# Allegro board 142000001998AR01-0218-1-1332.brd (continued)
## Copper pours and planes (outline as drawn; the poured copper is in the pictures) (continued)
GND on BOTTOM: 136.75,58.37 136.25,57.86 136.25,54.79 135.41,53.95 133.25,53.95 133.07,53.77 133.07,50.7 133.63,50.14 138.28,50.14 139.06,50.93 139.06,57.99 138.68,58.37
GND on BOTTOM: 71.4,25.48 71.07,25.81 71.07,27.25 71.27,27.46 83.41,27.46 83.59,27.28 83.59,25.43 82.73,24.56 73.15,24.56 72.24,25.48
GND on BOTTOM: 79.27,62.2 82.55,62.2 84.28,60.48 84.28,56.21 83.44,55.37 79.55,55.37 79.17,55.75 79.17,62.1
GND on BOTTOM: 166.12,29.34 166.12,31.5 167.08,32.46 167.08,34.29 167.59,34.8 170.66,34.8 170.94,34.52 170.94,31.85 171.65,31.14 172.36,31.14 173.05,30.45 173.05,29.69 172.29,28.93 166.52,28.93
GND on BOTTOM: 72.77,22.4 66.47,22.4 65.86,21.79 64.57,21.79 64.41,21.64 64.41,20.88 64.52,20.78 72.8,20.78 72.9,20.88 72.9,22.28
GND on BOTTOM: 26.04,25.02 30.61,25.02 31.5,24.13 31.5,23.37 30.99,22.86 29.46,22.86 29.08,22.48 29.08,21.84 28.7,21.46 25.78,21.46 25.4,21.84 25.4,24.38
GND on BOTTOM: 1.68,16.66 7.39,16.66 7.92,16.13 7.92,11.28 7.34,10.69 2.36,10.69 1.47,11.58 1.47,16.46
GND on BOTTOM: 175.03,83.19 175.03,82.37 174.9,82.25 174.19,82.25 173.74,82.7 172.82,82.7 172.72,82.8 172.72,86.51 173,86.79 175.06,86.79 175.29,86.56 175.29,85.85 174.96,85.52 174.19,85.52 173.96,85.29 173.96,83.44 174.17,83.24 174.98,83.24
GND on BOTTOM: 164.77,35.81 164.77,42.82 165.28,43.33 165.28,45.69 165.48,45.9 166.29,45.9 166.47,46.08 166.47,48.59 165.71,49.35 165.71,50.6 165.99,50.88 168.73,50.88 170.51,49.1 170.51,44.3 168.61,42.39 166.62,42.39 166.27,42.04 166.27,35.97 165.89,35.59 165,35.59
GND on BOTTOM: 44.88,27.53 55.78,27.53 56.79,28.55 56.79,33.45 57.18,33.83 57.18,36.04 57.19,36.06 57.19,37.4 57.4,37.62 58.55,37.62 58.83,37.34 58.83,23.9 56.52,21.59 55.65,21.59 55.52,21.72 55.52,24.21 56.36,25.04 56.36,25.45 56.03,25.78 55.58,25.78 54.58,24.79 53.85,24.79 52.68,23.62 48.74,23.62 48.26,23.14 48.26,22.15 47.73,21.62 44.63,21.62 43.97,22.28 43.97,25.58 44.36,25.97 44.36,27.01
GND on BOTTOM: 111.56,71.68 110.92,71.68 110.87,71.73 110.87,74.02 111.05,74.19 113.49,74.19 113.77,74.47 113.77,77.17 113.06,77.88 113.06,79.38 112.8,79.63 110.67,79.63 110.54,79.76 110.54,80.06 110.69,80.21 116.03,80.21 116.54,79.71 116.54,73.08 120.32,69.29 120.32,68.43 119.46,67.56 115.32,67.56 114.76,68.12 114.76,72.11 114.02,72.85 112.73,72.85
GND on BOTTOM: 96.39,51.99 97.59,51.99 97.92,51.66 97.92,50.34 97.56,49.99 96.6,49.99 96.29,50.29 96.29,51.89
GND on BOTTOM: 41.5,14.96 47.4,14.96 47.98,14.38 47.98,12.65 46.84,11.51 42.16,11.51 41.1,12.57 41.1,14.55
GND on BOTTOM: 90.47,52.63 91.82,52.63 92.15,52.3 92.15,48.9 92.02,48.77 91.39,48.77 90.83,49.33 89.66,49.33 89.08,48.74 89.08,46.91 88.62,46.46 88.06,46.46 87.68,46.84 87.68,49.83
GND on BOTTOM: 162.69,10.19 167.34,10.19 167.49,10.03 167.49,8.81 167.06,8.38 167.06,5.13 166.7,4.78 163.32,4.78 162.41,5.69 162.41,9.91
GND on BOTTOM: 77.83,44.25 78.05,44.02 78.05,42.65 84.1,36.6 84.1,35.79 84.02,35.71 73.2,35.71 72.95,35.46 72.95,34.8 72.85,34.7 69.01,34.7 68.3,33.99 65.94,33.99 65.79,34.14 65.79,35.62 69.29,39.13 69.29,43.74 69.8,44.25
GND on BOTTOM: 187.74,116.66 189.69,116.66 190.01,116.34 190.01,112.81 189.76,112.56 187.12,112.56 186.84,112.84 186.84,115.76
GND on BOTTOM: 7.03,91.27 7.03,95.54 8.34,96.86 14.9,96.86 15.72,96.03 15.72,91.08 13.54,88.9 9.41,88.9
GND on G2: 0.26,0.26 0.26,123.24 209.7,123.24 209.73,123.22 209.73,0.3 209.68,0.26
GND on G4, G9: 0.26,0.26 0.26,123.24 209.7,123.24 209.73,123.22 209.73,0.3 209.68,0.26
GND on S5: 101.28,75.76 101.28,74.65 101,74.37 97.69,74.37 97.13,73.81 97.13,72.19 97.51,71.81 101.96,71.81 102.11,71.65 102.11,71.4 101.57,70.87 101.57,69.47 101.32,69.22 100.71,69.22 99.95,68.45 99.95,64.47 99.62,64.13 96.52,64.13 96.47,64.14 86.49,64.14 84.71,62.36 84.71,58.55 83.95,57.78 80.14,57.78 79.38,58.55 79.38,77.22 80.52,78.36 85.47,78.36 86.11,78.99 86.11,82.68 86.23,82.8 93.22,82.8 93.47,82.55 93.47,80.9 94.49,79.88 99.82,79.88 100.33,79.38 100.33,76.71
GND on V6: 55.65,37.19 54.05,37.19 53.3,37.93 38.76,37.93 38.08,38.61 32.59,38.61 30.84,40.36 30.84,52.45 30.2,53.09 2.06,53.09 0.69,51.71 0.38,51.71 0.3,51.79 0.3,86.44 2.79,83.95 27,83.95 28.91,85.85 28.91,107.85 32.08,111.02 55.85,111.02 61.09,105.79 65.66,105.79 68.71,102.74 68.71,100.84 70.87,98.68 93.73,98.68 95.15,97.26 95.15,93.7 96.27,92.58 96.27,88.27 93.85,85.85 93.85,85.8 93.22,85.17 93.22,73.28 92.84,72.9 88.9,72.9 88.39,72.39 88.39,71.45 88.9,70.94 88.9,70.79 88.39,70.28 88.39,68.28 88.9,67.77 88.9,67.41 88.39,66.9 88.39,66.42 90.55,64.26 92.28,64.26 92.89,63.65 92.89,63.02 92.71,62.84 92.71,62.28 92.89,62.1 92.89,61.62 92.69,61.43 92.69,60.33 93.14,59.88 93.14,51.1 77.09,35.05 57.78,35.05
GND on V6: 0.33,0.28 0.29,0.29 0.28,0.33 0.28,123.17 0.29,123.21 0.33,123.22 141.94,123.22 141.94,122.59 0.91,122.59 0.91,0.91 126.16,0.91 126.59,0.48 127.23,0.48 127.66,0.91 160.05,0.91 160.48,0.48 161.14,0.48 161.57,0.91 185.09,0.91 207.85,0.91 208.33,1.4 208.33,122.02 207.77,122.59 151.51,122.59 151.51,123.22 209.67,123.22 209.73,123.16 209.73,0.33 209.68,0.28
GND on V6, V7: 141.17,122.59 142.39,122.59 143.46,121.51 151.58,121.51 152.65,122.59 152.78,122.59 152.78,123.22 141.17,123.22
GND on V7: 6.35,122.43 6.86,121.92 6.86,109.6 11.94,104.52 12.45,104.52 12.57,104.65 51.56,104.65 51.82,104.9 56.39,104.9 59.44,107.95 60.07,107.95 62.1,109.98 70.74,109.98 71.5,109.22 71.5,107.19 74.42,104.27 79.25,104.27 93.85,89.66 93.85,85.98 94.49,85.34 97.16,85.34 97.54,84.96 97.54,84.2 95,81.66 93.47,81.66 92.96,81.15 92.96,74.3 92.58,73.91 86.36,73.91 85.98,74.3 85.98,76.33 84.71,77.6 84.71,78.87 83.82,79.76 78.87,79.76 76.33,77.22 76.33,75.69 75.82,75.18 72.77,75.18 72.26,74.68 69.09,74.68 68.71,74.3 63.75,74.3 62.87,75.18 49.78,75.18 48.9,76.07 42.93,76.07 41.78,77.22 27.94,77.22 27.56,77.6 22.73,77.6 19.81,74.68 19.81,59.82 20.19,59.44 19.81,59.05 19.81,58.04 20.19,57.66 19.81,57.28 19.81,40.01 19.43,39.62 10.54,39.62 8.64,41.53 8.64,105.41 6.22,107.82 1.14,107.82 1.04,107.92 1.04,121.95 1.52,122.43 ; 1 cut-out
GND on V7: 34.11,57.14 35.36,57.14 35.83,56.67 38.14,56.67 38.61,57.14 70.47,57.14 71.34,58.01 77.3,58.01 77.49,57.82 77.49,57.44 66.01,45.96 63.26,45.96 60.37,43.07 60.37,40.51 59.14,39.28 34.9,39.28 32.92,41.26 32.92,55.95
GND on V7: 0.33,0.28 0.29,0.29 0.28,0.33 0.28,123.17 0.29,123.21 0.33,123.22 141.91,123.22 141.91,122.59 0.91,122.59 0.91,0.91 126.16,0.91 126.59,0.48 127.23,0.48 127.66,0.91 160.05,0.91 160.48,0.48 161.14,0.48 161.57,0.91 185.09,0.91 207.85,0.91 208.33,1.4 208.33,122.02 207.77,122.58 185.09,122.58 185.09,122.59 151.54,122.59 151.54,123.22 185.67,123.22 185.67,123.22 209.68,123.22 209.73,123.16 209.73,0.36 209.65,0.28
GND on G11: 185.74,0.26 0.26,0.26 0.26,123.24 185.74,123.24 185.74,123.24 209.7,123.24 209.73,123.22 209.73,0.3 209.68,0.25 185.75,0.25
GND_SCREW1 on TOP (solid shape): outline of 235 points within 6.1,1.5 13.1,8.5
GND_SCREW1 on BOTTOM (solid shape): outline of 235 points within 6.1,1.5 13.1,8.5
GND_SCREW2 on TOP (solid shape): outline of 235 points within 172.9,106.62 179.9,113.63
GND_SCREW2 on BOTTOM (solid shape): outline of 235 points within 172.9,106.62 179.9,113.63
GND_SCREW3 on TOP (solid shape): outline of 235 points within 172.9,1.5 179.9,8.5
GND_SCREW3 on BOTTOM (solid shape): outline of 235 points within 172.9,1.5 179.9,8.5
GND_SCREW4 on TOP (solid shape): outline of 235 points within 50.02,106.62 57.03,113.63
GND_SCREW4 on BOTTOM (solid shape): outline of 235 points within 50.02,106.62 57.03,113.63
GND_SCREW5 on TOP (solid shape): outline of 235 points within 87.2,1.5 94.2,8.5
GND_SCREW5 on BOTTOM (solid shape): outline of 235 points within 87.2,1.5 94.2,8.5
P0V6_VTT on BOTTOM: 38.91,31.09 39.14,31.32 40.61,31.32 40.82,31.11 40.82,30.86 40.77,30.81 39.83,30.81 39.78,30.76 39.78,30.25 39.8,30.23 40.74,30.23 40.82,30.15 40.82,29.9 40.72,29.79 39.45,29.79 39.22,30.02 35.94,30.02 35.18,29.26 34.59,29.26 33.96,29.9 33.96,30.94 34.11,31.09
P0V6_VTT on V6: 55.27,28.85 56.67,30.25 56.67,35.66 55.37,36.96 53.59,36.96 52.68,37.87 34.85,37.87 33.86,36.88 33.86,29.84 34.85,28.85
P0V9_A_L_I210 on BOTTOM: 135.13,84.84 136.65,84.84 136.91,84.58 136.91,82.8 136.65,82.55 135.38,82.55 134.87,83.06 134.87,84.58
P0V9_A_L_I210 on S5: 135.71,80.72 134.57,81.86 134.57,93.85 135,94.28 135,96.55 135.53,97.08 153.52,97.08 156.01,94.59 156.01,83.31 153.42,80.72
P1V2_VDDQ on TOP: 45.09,28.55 44.63,29.01 44.63,32.05 48.16,35.59 54.18,35.59 54.66,36.07 54.66,43.38 55.4,44.12 55.4,49.81 63.02,57.43 74.98,57.43 75.49,56.92 75.49,55.58 73.74,53.82 65.18,53.82 60.35,49 60.35,44.42 59.28,43.36 59.28,37.39 60.83,35.84 60.83,30.78 60.45,30.4 55.93,30.4 54.08,28.55
P1V2_VDDQ on TOP: 79.35,73.2 79.35,74.98 79.48,75.11 79.6,75.11 79.86,74.85 79.86,72.82 80.11,72.57 80.49,72.57 80.49,72.19 80.37,72.06 80.11,72.06 79.86,71.8 79.86,71.17 79.98,71.04 80.24,71.04 80.49,70.79 80.49,70.53 80.37,70.41 80.11,70.41 79.98,70.28 79.98,69.65 80.49,69.14 80.49,68.76 80.37,68.63 80.11,68.63 79.98,68.5 79.98,67.87 80.37,67.49 80.49,67.49 80.49,67.11 80.37,66.98 79.98,66.98 79.86,66.85 79.86,66.42 80.31,65.96 81.1,65.96 81.56,65.51 81.56,65.15 81.94,64.77 81.94,64.51 81.84,64.41 81.46,64.41 80.62,65.25 80.19,65.25 79.86,64.92 79.86,64.13 79.6,63.88 79.4,63.88 79.35,63.93 79.35,68.5 79.1,68.76 79.1,69.01 79.35,69.26 79.35,71.8 78.97,72.19 78.97,72.82
P1V2_VDDQ on BOTTOM: 45.52,32.87 53.87,32.87 54.76,33.76 54.76,38.02 55.02,38.28 55.88,38.28 56.13,38.02 56.13,29.87 54.81,28.55 45.09,28.55 44.63,29.01 44.63,29.59 45.02,29.98 45.02,32.37
P1V2_VDDQ on BOTTOM: 74.14,55.65 78.21,55.65 78.54,55.98 78.54,63.42 78.26,63.7 76.97,63.7 76.1,62.82 76.1,59.69 73.96,57.56 73.96,55.83
P1V2_VDDQ on G2: 84.45,64.49 84.09,64.13 81.24,64.13 81.2,64.09 80.22,64.09 79.45,63.32 79.45,61.23 78.3,60.07 76.96,60.07 76.18,60.85 74.35,60.85 73.84,61.37 73.36,61.37 73.2,61.52 73.2,62 72.97,62.23 66.7,62.23 63.91,59.44 57.73,59.44 57.02,60.15 54.46,60.15 53.75,59.44 48.51,59.44 48.39,59.31 47.43,59.31 47.4,59.28 32.16,59.28 30.73,60.71 30.73,75.82 31.51,76.6 44.57,76.6 45.39,77.42 46.74,77.42 46.89,77.57 51.77,77.57 52.27,78.08 53.98,78.08 54.58,77.47 55.73,77.47 56.34,78.08 64.06,78.08 65.3,76.83 66.12,76.83 67.82,75.13 73.47,75.13 73.93,75.59 74.16,75.59 74.62,75.13 77.44,75.13 78.26,74.32 79.63,74.32 79.83,74.52 79.83,77.9 81.43,79.5 83.62,79.5 84.45,78.66 84.45,74.5 85.01,73.94 85.01,70.51 84.45,69.95
P1V2_VDDQ on G4: 84.45,72.85 83.97,72.36 83.97,70.56 84.45,70.08 84.45,64.49 84.09,64.13 81.24,64.13 81.2,64.09 80.22,64.09 76.58,60.45 75.06,60.45 74.55,59.94 68.83,59.94 67.41,58.52 63.81,58.52 63.56,58.27 55.39,58.27 54.23,59.44 48.51,59.44 48.39,59.31 47.43,59.31 47.4,59.28 32.16,59.28 30.73,60.71 30.73,75.82 31.51,76.6 38.12,76.6 41.85,80.33 52.31,80.33 53.26,81.28 65.01,81.28 65.67,80.61 67.98,80.61 70.36,78.23 80.14,78.23 80.39,77.98 84.07,77.98 84.45,77.6
P1V2_VDDQ on S5: 35.79,37.49 55.17,37.49 56.72,35.94 56.72,27.94 58.65,26.01 60.76,26.01 61.16,25.6 61.16,15.75 60.86,15.44 59.08,15.44 58.78,15.75 58.78,17.78 51.97,24.59 23.7,24.59 20.6,27.69 20.6,77.8 22.73,79.93 43.87,79.93 44.32,79.48 44.32,70.13 43.64,69.44 43.64,67.72 43.99,67.36 43.99,67.03 43.64,66.67 43.64,62.64 44.15,62.13 44.15,51.71 40.69,48.26 34.98,48.26 32.82,46.1 32.82,40.46
P1V2_VDDQ on V7: 84.45,76.3 85.45,75.31 85.45,74.27 84.45,73.28 84.45,64.49 84.09,64.13 84.09,63.98 78.44,58.32 69.62,58.32 68.83,57.53 32.99,57.53 31.72,56.26 31.72,40.56 30.33,39.17 22.07,39.17 20.5,40.74 20.5,74.22 22.88,76.6 38.12,76.6 38.13,76.61 41.33,76.61 42.32,75.62 48.56,75.62 49.4,74.78 62.76,74.78 63.45,74.09 68.86,74.09 69.19,74.42 72.34,74.42 72.64,74.73 76.45,74.73 76.86,75.13 76.86,76.83 79.15,79.12 83.69,79.12 84.45,78.36
P1V2_VDDQ on S8: 38.51,39.6 54.05,39.6 56.72,36.93 56.72,31.37 55.3,29.95 44.04,29.95 41.58,27.48 28.96,27.48 27.56,28.88 27.56,53.59 30.86,56.9 30.86,76.02 31.37,76.53 33.55,76.53 34.06,76.02 34.06,63.6 36.55,61.11 36.55,55.07 32.82,51.33 32.82,45.29
P1V2_VDDQ on G9: 84.45,76.05 85.29,75.21 85.29,74.42 84.45,73.58 84.45,72.87 85.09,72.24 85.09,70.56 84.45,69.93 84.45,64.49 84.17,64.05 80.06,59.94 66.76,59.94 66.25,59.44 57.33,59.44 56.85,59.92 54.71,59.92 54.23,59.44 48.51,59.44 48.39,59.31 47.43,59.31 47.4,59.28 32.16,59.28 30.73,60.71 30.73,75.82 31.31,76.39 41.24,76.39 41.63,76 46.94,76 47.36,75.58 48.68,75.58 49.56,74.7 62.64,74.7 63.22,74.12 68.81,74.12 69.24,74.55 76.38,74.55 76.86,75.03 76.86,78 78.46,79.6 83.21,79.6 84.45,78.36
P1V2_VDDQ on G11: 84.45,76.94 84.45,74.47 85.01,73.91 85.01,70.46 84.45,69.9 84.45,64.49 84.09,64.13 81.24,64.13 81.2,64.09 80.22,64.09 77.52,61.39 73.1,61.39 73.03,61.47 70.13,61.47 69.8,61.14 65.66,61.14 63.96,59.44 57.76,59.44 57.28,59.92 54.51,59.92 54.03,59.44 48.51,59.44 48.39,59.31 47.43,59.31 47.4,59.28 32.16,59.28 30.99,60.45 30.99,75.79 31.39,76.2 46.53,76.2 47.22,75.51 57.51,75.51 59.08,77.09 70.76,77.09 70.99,76.86 75.72,76.86 75.73,76.87 75.96,76.87 76.15,77.06 76.15,77.29 77.15,78.3 80.28,78.3 80.47,78.11 81.97,78.11 82.07,78.21 82.45,78.21 82.6,78.05 83.34,78.05
P1V05 on TOP: 127.76,81.28 127.76,79.96 127.25,79.45 126.31,79.45 124.99,78.13 124.99,75.64 124.56,75.21 122.43,75.21 122.17,75.46 122.17,79.5 122.43,79.76 123.57,79.76 123.95,80.14 123.95,81.15 124.17,81.37 125.39,81.37 125.77,81.75 127.29,81.75
P1V05 on TOP: 132.77,63.88 134.49,63.88 134.72,63.65 134.72,59.61 134.14,59.03 132.94,59.03 132.59,59.39 132.59,63.7
P1V05 on TOP, BOTTOM: 106.93,33.5 102.74,33.5 102.25,33.01 101.59,33.01 101.22,32.64 101.22,27.43 102.11,26.54 114.05,26.54 114.3,26.8 114.3,28.57 114.55,28.83 120.52,28.83 120.9,29.21 120.9,34.29 120.52,34.67 115.19,34.67 113.79,33.27 107.16,33.27
P1V05 on BOTTOM: 120.9,79.17 125.09,79.17 125.55,78.71 125.55,76.4 124.16,75.01 122.48,75.01 120.93,73.46 119.13,73.46 118.54,74.04 117.6,74.04 117.37,74.27 117.37,75.92 117.63,76.17 119.96,76.17 120.42,76.63 120.42,78.69
P1V05 on S5: 71.25,109.22 71.63,108.84 71.63,107.31 71.12,106.81 61.59,106.81 59.94,105.16 20.7,105.16 19.05,106.81 19.05,108.97 19.43,109.35 47.75,109.35 50.55,106.55 56.52,106.55 59.18,109.22
P1V05 on S5: 104.01,73.25 120.17,73.25 122.4,71.02 122.4,69.72 122.05,69.37 120.02,69.37 119.51,69.88 110.06,69.88 109.7,69.52 102.54,69.52 102.11,69.95 102.11,70.87 102.37,71.13 102.37,71.62
P1V05 on V6: 121.03,69.34 120.78,69.6 120.78,78.99 121.67,79.88 124.51,79.88 126.42,81.79 132.79,81.79 145.75,68.83 169.24,68.83 169.98,69.57 169.98,78.21 170.21,78.44 172.82,78.44 173.05,78.21 173.05,68.86 173.66,68.25 178.05,68.25 178.64,67.67 178.64,46.89 177.93,46.18 170.87,46.18 170.18,46.86 170.18,59.39 169.49,60.07 141.3,60.07 132.03,69.34
P1V05 on V7: outline of 104 points within 7.42,5.33 178.61,122.22
P1V5_A_L_I210 on S5: 144.96,88.42 145.68,89.15 148.67,89.15 149.05,88.77 149.05,85.01 148.5,84.47 139.78,84.47 139.26,85 139.26,86.04 139.23,86.07 139.23,87.59 140.06,88.42
P1V5_PCH on TOP: 130.05,74.55 130.05,73.15 129.79,72.9 125.86,72.9 125.48,73.28 125.48,75.92 125.65,76.1 128.32,76.1 128.47,75.95 128.47,75.41 129.21,74.68 129.92,74.68
P1V05_PCH on TOP: 120.85,83.24 121.03,83.41 121.03,83.97 121.31,84.25 124.89,84.25 125.22,83.92 125.22,82.35 124.92,82.04 114.25,82.04 113.87,82.42 113.87,82.88 114.22,83.24
P1V05_PCH on BOTTOM: 115.63,84.97 116.72,86.06 124.49,86.06 125.41,85.15 125.41,82.24 124.75,81.58 117.74,81.58 117.31,82 115.91,82 115.51,82.4 114.57,82.4 114.33,82.17 109.79,82.17 109.37,82.59 109.37,84.8 109.55,84.98 110.12,84.98 110.25,84.84 110.25,84.32 110.34,84.24 112.12,84.24 112.29,84.41 112.29,84.82 112.44,84.97
P1V5_PCH on S3: 128.63,73.99 127.79,73.15 125.76,73.15 118.59,80.31 117.07,80.31 114.25,83.13 109.96,83.13 107.7,80.87 107.7,76.2 107.06,75.56 95.07,75.56 94.77,75.87 94.77,77.55 95.73,78.51 98.42,78.51 99.95,80.04 99.95,89.53 101.6,91.19 103.5,91.19 104.27,91.95 104.27,99.97 104.7,100.41 111.35,100.41 122.03,89.73 122.85,89.73 123.9,88.67 123.9,87.86 126.39,85.37 126.39,84.73 126.85,84.28 127.48,84.28 128.63,83.13
P1V05_PCH on S5: 107.95,82.04 107.31,81.41 104.62,81.41 104.14,80.92 100.79,80.92 100.51,81.2 100.51,84.48 101.37,85.34 101.98,85.34 102.87,86.23 111.89,86.23 112.37,86.71 123.47,86.71 123.52,86.66 123.52,82.4 123.16,82.04
P1V05_PCH on V7: 109.92,85 109.98,85 111.7,86.72 113.15,86.72 114.21,87.77 114.88,87.77 115.94,86.72 123.16,86.72 123.5,86.37 123.5,82.17 121.64,80.31 121.27,80.31 120.12,79.16 111.06,79.16 111.02,79.12 101.42,79.12 98.93,81.61 98.93,83.82 98.3,84.45 98.3,85.47 98.42,85.6 99.44,85.6 99.69,85.34 99.69,84.96 100.71,83.95 108.87,83.95
P1V05_PCH on S10: 102.55,82.52 103.63,81.44 103.63,80.64 101.37,78.38 101.37,70.74 100.69,70.05 100.13,70.05 99.59,70.59 99.59,76.25 98.42,77.42 98.42,78.77 97.97,79.22 97.33,79.22 97.32,79.21 96.69,79.21 96.39,79.5 96.39,80.01 96.86,80.48 96.86,82.54 97.39,83.07 98.52,84.2 98.52,84.9 99.38,85.76 102.43,85.76 102.55,85.64
P1V05_VCC_PCH on TOP: 119.48,81.71 123.39,81.71 123.7,81.41 123.7,80.59 123.47,80.37 121.84,80.37 121.13,79.65 119.63,79.65 119.25,80.04 119.25,81.48
P1V05_VCC_PCH on V6: 123.94,86.62 125.35,85.22 125.35,81.46 124.28,80.39 121.69,80.39 120.93,79.63 119.68,79.63 119,80.31 117.65,80.31 116.54,79.2 101.09,79.2 100.37,79.92 98.49,79.92 98.11,80.3 98.11,81.25 98.7,81.85 98.7,84.09 98.35,84.45 98.35,87.43 100.2,89.28 113.16,89.28 115.82,86.61 121.54,86.61 121.79,86.62
P1V05_VCCGBE on TOP: 125.76,62.76 131.78,62.76 131.98,62.56 131.98,58.9 131.84,58.76 131.28,58.76 131.01,58.5 131.01,53.52 130.84,53.34 128.7,53.34 128.14,53.9 128.14,58.17 127.84,58.47 122.5,58.47 122.3,58.67 122.3,61.8 122.71,62.2 125.2,62.2
P1V05_VCCGBE on TOP: 106.17,68.88 106.17,68.05 106.05,67.92 104.27,67.92 103.17,69.01 103.17,69.54 103.3,69.67 104.33,69.67 104.47,69.53 104.81,69.53 105.03,69.32 105.33,69.32 105.44,69.42 105.64,69.42 105.74,69.32 106.12,69.32 106.25,69.44 106.38,69.44 106.43,69.39 106.43,68.91 106.4,68.88
P1V05_VCCGBE on TOP: 103.35,65.51 103.66,65.2 106.48,65.2 106.76,65.48 106.76,65.89 106.63,66.01 105.41,66.01 105.33,66.09 105.33,66.98 105.31,67 105.03,67 104.85,67.18 104.62,67.18 104.47,67.03 104.19,67.03 104.06,67.16 103.84,67.16 103.68,67 103.68,66.75 103.81,66.62 103.81,66.24 103.43,65.86 103.38,65.86 103.35,65.84
P1V05_VCCGBE on BOTTOM: 104.75,68.22 105.59,68.22 105.84,68.48 105.84,69.37 105.59,69.62 104.75,69.62 104.5,69.37 104.5,68.48
P1V05_VCCGBE on BOTTOM: 104.83,65.66 105.03,65.86 105.03,67.11 104.9,67.23 103.86,67.23 103.61,66.98 103.61,65.79 103.73,65.66
P1V05_VCCGBE on BOTTOM: 123.01,62.2 129.64,62.2 130.53,61.32 130.53,57.89 130.89,57.53 132.84,57.53 132.84,54.51 132.41,54.08 132.41,50.67 131.98,50.24 129.95,50.24 128.14,52.04 128.14,58.14 127.81,58.47 123.44,58.47 122.83,59.08 122.83,62.03
P1V05_VCCGBE on V6: 131.42,63.32 131.42,60.93 130.48,59.99 108.26,59.99 102.93,65.32 102.93,68.64 103.89,69.6 118.24,69.6 118.87,68.96 128.02,68.96 129.2,67.78 129.2,65.54
P1V05_VCCGBE on V7: 130.76,64.67 130.76,60.76 129.88,59.87 125.22,59.87 118.4,66.69 109.46,66.69 108.13,65.35 108.13,61.49 108.79,60.83 113.13,60.83 113.45,60.51 113.45,55.37 113.11,55.03 107.73,55.03 105.15,57.61 105.15,59.48 103.9,60.73 103.9,62.12 102.93,63.09 102.93,68.64 103.89,69.6 119.11,69.6 119.75,68.96 126.47,68.96
P1V05_VCCGBE on S8: 105.28,67.6 105.41,67.73 105.41,68.07 105.79,68.45 105.79,69.76 104.52,71.03 104.52,73.76 104.46,73.82 102.87,73.82 102.81,73.76 102.81,65.98 103.02,65.76 104.49,65.76 105.28,66.55
P1V05_VCCGBE on S10: 103.23,65.41 104.01,64.62 106.43,64.62 107.01,65.2 107.01,68.05 107.59,68.63 112.37,68.63 121.67,59.33 131.24,59.33 131.67,59.77 131.67,65.46 130.33,66.8 126.36,66.8 119.39,73.77 119.39,76.77 117.98,78.18 110.24,78.18 109.78,78.64 108.18,78.64 108.18,78.26 108.1,78.18 104.09,78.18 103.23,77.32
P1V05_VCCION on TOP: 120.47,77.39 121.28,77.39 121.49,77.19 121.49,75.01 121.02,74.54 119.01,74.54 118.69,74.85 118.69,75.77 118.97,76.05 119.84,76.05 120.42,76.63 120.42,77.34
P1V05_VCCION on V6: 97.79,81.15 97.79,79.92 98.04,79.67 99.57,79.67 99.57,79.63 99.95,79.63 100.97,78.61 110.36,78.61 111.12,77.85 119.76,77.85 120.02,77.6 120.02,76.83 120.14,76.71 120.14,74.73 119.96,74.55 103.63,74.55 102.68,73.6 102.68,67.28 102.55,67.16 99.12,67.16 94.95,71.33 94.95,72.56 93.42,74.09 93.42,82.37 93.94,82.89 96.98,82.89 98.02,83.92 98.48,83.92 98.6,83.79 98.6,81.97
P1V05_VCCION on V7: 98.54,79.67 99.57,79.67 99.57,79.63 99.95,79.63 100.59,78.99 118.63,78.99 120.02,77.6 120.02,76.83 120.14,76.71 120.14,74.75 119.94,74.55 103.63,74.55 102.68,73.6 102.68,63.16 102.93,62.91 102.93,61.67 102.86,61.6 102.41,61.6 101.4,62.61 99.83,62.61 99.54,62.9 99.54,65.78 98.63,66.68 98.63,67.65 94.95,71.33 94.95,72.56 93.34,74.17 93.34,80.52 93.85,81.03 95.12,81.03 98.17,84.07 98.55,84.07 98.81,83.82 98.81,82.17 98.17,81.53 98.17,80.04
P1V05_VCCION on S8: 101.85,69.44 99.69,69.44 98.97,68.72 98.97,67.56 99.31,67.22 102.23,67.22 102.55,67.54 102.55,68.74
P1V05_VCCSCSUS on TOP: 104.65,69.9 104.89,69.9 104.89,69.9 104.97,69.9 105.01,69.86 105.01,69.59 105.04,69.55 105.24,69.55 105.59,69.9 105.74,69.9 105.8,69.84 105.8,69.68 105.87,69.61 106.02,69.61 106.08,69.67 106.08,69.84 106.15,69.9 106.45,69.9 106.71,69.64 106.8,69.64 106.93,69.77 106.93,70.79 106.55,71.18 104.52,71.18 104.47,71.13 104.47,70.08
P1V05_VCCSCSUS on BOTTOM: 109.25,73.99 110.16,73.99 110.24,73.91 110.24,71.86 109.02,70.64 107.09,70.64 106.78,70.33 106.78,70.13 106.53,69.88 104.27,69.88 104.09,70.05 104.09,70.99 104.55,71.45 105.84,71.45 106.38,71.98 107.42,71.98 107.89,72.45 108.37,72.45 108.97,73.05 108.97,73.71
P1V05_VCCSCSUS on BOTTOM: 117.55,73.46 118.87,73.46 119.1,73.23 120.88,73.23 121.18,72.92 121.18,70.51 120.85,70.18 119.76,70.18 117.45,72.49 117.45,73.36
P1V05_VCCSCSUS on V6: 119.89,69.85 103.38,69.85 102.93,70.29 102.93,73.15 104.08,74.3 119.13,74.3 120.57,72.85 120.57,70.54
P1V05_VCCSCSUS on V7: 119.74,69.7 103.53,69.7 102.93,70.29 102.93,73.15 104.08,74.3 119.13,74.3 120.27,73.15 120.27,70.23
P1V7_SW on TOP: 168.2,67.54 164.49,67.54 162.53,69.49 160.91,69.49 160.83,69.57 160.83,70.54 160.91,70.61 168.1,70.61 168.38,70.33 168.38,67.72
P3V3 on TOP (solid shape): 160.53,107.31 160.53,106.68 160.27,106.43 157.86,106.43 157.61,106.68 157.61,107.31 157.86,107.57 160.27,107.57
P3V3 on TOP: 144.78,56.13 144.4,55.75 144.4,49.4 145.03,48.77 157.71,48.77 162.36,53.42 162.36,55.83 162.05,56.13
P3V3 on TOP: 203.54,74.43 205.37,74.43 205.53,74.59 205.53,76.17 205.32,76.38 203.38,76.38 203.1,76.1 203.1,74.87
P3V3 on BOTTOM: 98.55,73.99 97.46,73.99 97.13,74.32 96.14,74.32 96.04,74.22 96.04,73.53 96.22,73.36 97.16,73.36 97.38,73.13 97.38,72.72 97.46,72.64 98.63,72.64 98.76,72.77 98.76,73.79
P3V3 on S3: 20.73,122.33 31.75,122.33 32.26,121.82 32.26,109.7 30.48,107.92 21.89,107.92 21.39,108.43 21.39,119.89 20.45,120.83 20.45,122.05
P3V3 on S5: 126.97,84.15 126.97,79.3 121.11,73.43 103.86,73.43 102.49,72.06 97.56,72.06 97.38,72.24 97.38,73.66 97.69,73.96 101.88,73.96 102.39,74.47 102.39,76.3 103,76.91 118.9,76.91 120.29,78.31 120.29,79.72 121.5,80.93 122.91,80.93 123.9,81.92 123.9,84.3 124.18,84.58 126.54,84.58
P3V3 on V6: outline of 131 points within 1.5,1.14 208.08,122.68 ; 1 cut-out
P3V3_A on TOP: 158.85,39.52 158.85,48.18 162.15,51.49 163.91,51.49 164.62,50.77 164.62,39.78 163.98,39.14 159.23,39.14
P3V3_A on TOP: 174.47,98.76 179.58,98.76 179.96,98.37 179.96,96.01 177.93,93.98 176.15,93.98 174.22,95.91 174.22,98.5
P3V3_A on BOTTOM: 163.91,51.49 164.62,50.77 164.62,43.28 163.65,42.32 160.05,42.32 159.18,43.18 159.18,48.51 162.15,51.49
P3V3_A on V7: 177.04,122.1 175.77,120.83 175.77,78.84 179.24,75.37 179.24,46.58 178.14,45.49 139.19,45.49 137.79,44.09 137.79,26.19 136.53,24.92 96.55,24.92 87.6,15.98 57.66,15.98 46.74,5.05 23.34,5.05 22.23,6.17 22.23,13.67 23.83,15.27 42.37,15.27 53.67,26.57 87.96,26.57 93.68,32.28 93.68,36.45 93.31,36.82 91.17,36.82 90.63,36.27 90.63,33.27 86.39,29.03 64.65,29.03 63.72,29.95 63.72,36.7 63.41,37.01 62.21,37.01 60.26,38.96 10.31,38.96 8.08,41.2 8.08,105.11 6.05,107.14 2.39,107.14 1.09,105.84 1.09,1.93 2.03,0.99 80.16,0.99 80.37,1.19 207.57,1.19 207.95,1.57 207.95,121.84 207.7,122.1 ; 1 cut-out
P3V3_A_L_I210 on TOP: 176.28,102.36 176.28,100.2 176.15,100.08 171.95,100.08 171.86,100.16 169.33,100.16 167.51,101.98 167.51,103.12 167.77,103.38 175.26,103.38
P3V3_A_L_I210 on V7: 173.46,76.76 132.56,76.76 131.85,77.47 131.85,102.26 132.8,103.21 132.8,104.18 134.21,105.59 134.21,111.09 136.13,113.02 136.13,116.84 135.62,117.35 133.35,117.35 132.97,117.73 132.97,120.65 134.54,122.22 141.15,122.22 142.49,120.88 151.82,120.88 153.03,122.1 173.53,122.1 175.16,120.47 175.16,78.46
P3V3_BATT on S8: 94.01,84.45 92.08,86.39 92.08,90.93 93.73,92.58 93.73,92.61 95,93.88 95.81,93.88 96.14,93.55 96.14,92.68 95.86,92.41 95.86,91.72 96.75,90.83 96.75,85.14 96.06,84.45
P3V3_L_PCH on TOP: 106.71,7.39 106.71,6.02 106.2,5.51 103.73,5.51 103.68,5.56 103.68,6.6 104.8,7.72 104.8,10.31 105,10.52 107.87,10.52 108.1,10.29 108.1,8.79
P3V3_PCH on TOP: 108.86,4.72 107.39,4.72 107.04,4.37 107.04,3.99 106.83,3.78 103.91,3.78 103.68,3.56 103.68,3.02 103.89,2.82 104.27,2.82 104.44,2.64 104.44,1.55 104.62,1.37 108.1,1.37 108.33,1.6 108.33,3.1 108.46,3.23 108.79,3.23 108.99,3.43 108.99,4.6
P3V3_PCH on V7: 94.23,86.49 94.93,85.79 100.65,85.79 101.47,84.96 104.78,84.96 105,84.73 108.71,84.73 110.85,86.87 112.88,86.87 114.08,88.08 114.86,88.08 116.07,86.87 122.91,86.87 123.34,87.31 123.34,90.57 112.72,101.19 109.6,101.19 105.93,104.86 105.93,111.45 104.53,112.84 86.16,112.84 83.11,115.9 78.41,115.9 77.9,116.41 77.52,116.41 77.01,115.9 63.37,115.9 62.32,114.85 62.32,111.65 63.37,110.59 71.3,110.59 72.16,109.73 72.16,106.93 74.19,104.9 79.22,104.9 82.87,101.01 94.23,89.65 ; 1 cut-out
P3V3_PCH on S8: 98.79,76.31 98.93,76.17 103.38,76.17 104.14,76.94 104.14,86.69 103.76,87.07 98.76,87.07 98.16,86.47 98.16,84.57 98.16,84.57 98.16,83.27 97.42,82.54 96.25,82.54 94.61,80.9 94.61,80.04 94.84,79.81 95.4,79.81 96.09,79.12 97.74,79.12 98.79,78.07
P3V3_PCH on S8: 114.94,48.56 114.27,49.23 114.27,53.29 118.25,57.26 118.25,58.56 119.13,59.44 120.42,59.44 123.57,62.59 123.57,70.56 122.43,71.7 113.97,71.7 113.41,72.26 113.41,93.47 113.94,94.01 130.02,94.01 130.81,93.22 130.81,79.1 131.32,78.59 138.56,78.59 139.73,77.42 139.73,70.33 117.96,48.56 ; 1 cut-out
P3V3_PCH on S10: 114.78,51.77 114.78,50.16 115.67,49.28 115.67,45.92 109.89,40.14 109.89,18.35 102.01,10.46 102.01,3.02 102.95,2.08 108.88,2.08 109.14,2.34 109.14,6.88 110.26,8 112.19,8 115.39,11.2 115.39,31.72 117.97,34.3 117.97,51.02 116.87,52.12 115.14,52.12
P3V3_PCH on S10: 137.87,73.69 137.87,69.14 138.1,68.91 167.06,68.91 168.28,67.69 168.28,51.1 168.94,50.44 173.43,50.44 174.02,51.03 174.02,71.35 172.09,73.28 171.32,73.28 171.07,73.53 171.07,77.93 170.43,78.56 143.97,78.56 143.38,77.98 143.38,77.6 142.95,77.17 141.35,77.17
P3V3_PCH_L on TOP: 107.09,6.07 106.25,5.23 104.57,5.23 104.52,5.18 104.52,4.27 104.67,4.11 106.43,4.11 107.7,5.38 109.88,5.38 110.16,5.66 110.16,6.83 109.96,7.04 107.44,7.04 107.09,6.68
P3V3_STBY on BOTTOM: 10.34,16.26 19.28,16.26 20.19,17.17 22.83,17.17 23.01,16.99 23.01,15.27 22.3,14.55 12.29,14.55 11.53,13.79 10.21,13.79 9.96,14.05 9.96,15.88
P5V on TOP (solid shape): 163.83,109.6 163.83,108.2 163.58,107.95 162.56,107.95 162.31,107.7 162.31,106.68 162.05,106.43 161.16,106.43 160.78,106.81 160.78,107.7 160.91,107.82 160.91,109.47 161.29,109.86 163.58,109.86
P5V on TOP: 127.74,33.39 127.28,33.85 126.38,33.85 125.47,32.93 123.89,32.93 123.29,32.34 123.29,13.44 123.83,12.9 126.87,12.9 127.74,13.77
P5V on TOP: 168.02,75.41 164.49,75.41 164.31,75.59 164.31,77.22 164.57,77.47 169.52,77.47 169.83,77.16 169.83,73.57 169.57,73.3 168.68,73.3 168.28,73.71 168.28,75.16
P5V on TOP: 60.22,19.33 61.7,19.33 61.85,19.48 62.2,19.48 62.38,19.3 62.38,18.26 62.13,18.01 60.2,18.01 60.02,18.19 60.02,19.13
P5V on TOP: 122.15,119.35 131.7,119.35 131.9,119.15 131.9,115.32 131.46,114.88 130.61,114.88 130.43,115.06 130.43,115.47 130.38,115.53 127.65,115.53 126.77,116.41 122.63,116.41 120.85,114.63 115.95,114.63 115.67,114.91 115.67,117.96 115.87,118.16 120.95,118.16
P5V on TOP: 78.94,23.16 80.52,23.16 80.75,22.94 80.75,21.16 80.47,20.88 78.94,20.88 78.64,21.18 78.64,22.86
P5V on BOTTOM: 124.56,15.85 126.85,15.85 127.13,15.57 127.13,13.64 126.42,12.93 124.59,12.93 124,13.51 124,13.82 124.38,14.2 124.38,15.67
P5V on S5: 122.74,118.44 122.28,117.97 122.28,97.13 122.29,97.12 122.29,95.75 127.46,90.58 127.46,73.39 132.36,68.49 156.51,68.49 157.23,67.77 157.23,34.9 157.2,34.9 156.24,33.93 125.27,33.93 123.71,32.37 123.77,32.31 123.77,13.39 124.46,12.7 129.16,12.7 129.92,13.46 129.92,23.09 131.14,24.31 165,24.31 169.77,29.08 169.77,76.58 164.39,81.97 164.39,112.85 164.92,113.39 170.36,113.39 172.52,115.54 178.92,115.54 180.77,113.69 183.69,113.69 185.22,112.17 185.85,112.17 186.28,112.6 186.28,115.87 185.7,116.46 181.2,116.46 179.68,117.98 171.07,117.98 170.13,117.04 132.38,117.04 130.99,118.44
P5V on V6: 57.51,26.21 57.51,19.79 58.55,18.75 61.11,18.75 61.75,18.11 62.53,18.11 63.17,18.75 85.78,18.75 95.1,28.07 126.97,28.07 127.61,28.7 127.61,34.19 127,34.8 91.69,34.8 83.97,27.08 58.37,27.08
P5V on V7: 117.2,122.22 133.65,122.22 133.67,122.21 135.47,122.21 135.76,121.92 135.76,113.33 134.11,111.68 134.11,105.77 132.49,104.15 120.95,104.15 116.31,108.79 116.31,121.34
P5V_A on TOP: 87.76,19.08 88.98,19.08 89.15,18.9 89.15,18.44 88.95,18.24 87.78,18.24 87.68,18.34 87.68,19
P5V_A on TOP: 73.38,18.87 77.29,18.87 78.31,19.89 80.57,19.89 80.85,19.61 80.85,18.11 80.49,17.75 73.69,17.75 73.3,18.14 73.3,18.8
P5V_B on TOP: 120.57,17.17 120.57,16.46 120.68,16.36 120.9,16.36 121.06,16.21 121.06,13.84 121.13,13.77 121.54,13.77 121.74,13.97 121.74,16.99 121.51,17.22 120.62,17.22
P5V_CONN on BOTTOM: 157.48,6.17 159.51,6.17 159.69,6.35 159.69,10.44 159.99,10.74 167.39,10.74 167.56,10.92 167.56,12.12 167.34,12.34 157.56,12.34 157.38,12.17 157.38,6.27
P5V_STBY on TOP: 160.57,27.13 164.33,27.13 164.52,26.93 164.52,25.2 164.31,24.99 160.41,24.99 160.26,25.15 160.26,26.81
P5V_STBY on BOTTOM: 170.46,6.87 170.46,4.62 170.1,4.27 168.22,4.27 167.87,4.62 167.87,8.38 168.42,8.93 168.42,16.14 160.42,24.14 160.42,25.55 160.98,26.11 166.06,26.11 171.19,20.98 171.19,18.13 172.49,16.83 172.49,8.9
V1P8A on S10: 198.25,56.39 193.93,56.39 193.55,56.01 193.55,44.2 193.8,43.94 197.36,43.94 198.63,45.21 198.63,56.01
V3P3_SW on TOP: 155.57,46.74 155.96,46.35 155.96,43.56 155.7,43.31 153.29,43.31 153.11,43.13 153.11,40.59 153.03,40.51 152.1,40.51 151.97,40.64 151.97,43.1 151.76,43.31 149.35,43.31 149.1,43.56 149.1,46.35 149.48,46.74
V3P3A_SW on TOP: 166.6,34.52 166.6,33.48 166.5,33.38 158.8,33.38 158.47,33.71 158.47,35.59 158.9,36.02 163.58,36.02 165,34.59 166.52,34.59
V5A_PM_P1V7 on TOP: 165.33,71.42 160.81,71.42 160.63,71.6 160.63,74.19 160.96,74.52 165.81,74.52 166.04,74.3 166.04,72.14
V5A_SW on TOP: 119.94,112.39 120.8,111.53 123.47,111.53 123.52,111.48 123.52,110.52 123.44,110.44 121.56,110.44 119.84,108.71 116.11,108.71 115.72,109.1 115.72,112.22 115.9,112.39
V12A_CONN on TOP: 158.17,17.58 161.34,17.58 161.52,17.4 161.52,8.59 161.98,8.13 161.98,6.07 160.1,4.19 157.71,4.19 156.11,5.79 156.11,13.87 157.68,15.44 157.68,17.09
V12A_CONN on BOTTOM: 156.46,1.09 156.46,9.7 156.08,10.08 156.08,13.46 156.34,13.72 156.97,13.72 157.23,13.46 157.23,6.17 157.56,5.84 159.84,5.84 160.02,6.02 160.83,6.02 161.37,5.49 161.37,3.23 158.96,0.82 156.73,0.82
V12A_CONN_R on TOP: 167.39,22.94 167.87,22.45 167.87,16.22 167.02,15.37 162.59,15.37 162.28,15.67 162.28,17.58 162.81,18.11 164.1,18.11 164.34,18.35 164.34,22.61 164.67,22.94
V12A_DDR on TOP (solid shape): 55.77,19.21 54.3,19.21 54.3,20.84 55.77,20.84
V12A_DDR on BOTTOM (solid shape): 47.73,18.59 47.73,17.14 47.09,16.51 41.45,16.51 41.12,16.84 41.12,19.3 41.43,19.61 46.71,19.61
V12A_DDR on TOP: 55.85,20.78 55.85,19.1 55.58,18.82 55.17,18.82 54.13,17.78 49.78,17.78 48.62,18.95 48.62,20.5 48.74,20.62 52.32,20.62 52.58,20.88 55.75,20.88
V12A_DDR on TOP: 41.96,15.9 40.03,13.97 38.99,13.97 38.61,14.35 38.61,18.08 41.15,20.62 52.07,20.62 52.27,20.42 52.27,19.35 48.82,15.9
V12A_DDR on BOTTOM: 48.54,20.65 52.02,20.65 52.22,20.45 52.22,18.92 51.89,18.59 48.74,18.59 48.44,18.9 48.44,20.55
V12A_PM_V3P3A on TOP: 169.98,28.88 169.98,30.91 169.77,31.11 167.41,31.11 166.8,31.72 166.8,32.56 166.73,32.64 165.1,32.64 164.26,31.8 164.26,29.83 164.05,29.62 162.72,29.62 162.59,29.49 162.59,28.04 162.76,27.87 165.21,27.87 166.15,28.8 169.9,28.8
V12A_V3P3 on TOP: 151.16,42.21 151.16,40.67 151.05,40.56 149.53,40.56 149.33,40.77 146.41,40.77 145.92,40.28 144.75,40.28 144.55,40.49 144.55,43.28 144.78,43.51 147.57,43.51 148.51,42.57 150.8,42.57
V12A_V5A on TOP: 117.81,107.95 118.06,107.7 119.84,107.7 119.9,107.76 120.82,107.76 121.46,108.4 121.46,109.1 121.94,109.59 123.54,109.59 123.65,109.48 123.65,107.28 122.69,106.32 119.56,106.32 119.08,105.84 115.65,105.84 115.4,105.59 114.22,105.59 114.1,105.71 114.1,107.74 114.3,107.95
VCC12A on TOP: 161.29,18.85 149.68,18.85 149.1,19.43 149.1,22.48 149.86,23.24 161.16,23.24 161.67,22.73 161.67,19.23
VCC12A on TOP: 36.25,17.86 36.96,17.14 36.96,14.3 36.42,13.77 35.18,13.77 34.77,14.17 34.77,15.14 34.49,15.42 31.42,15.42 31.14,15.7 31.14,17.55 31.45,17.86
VCC12A on TOP: 18.24,18.49 23.04,18.49 23.24,18.29 23.24,16.23 22.71,15.7 19.23,15.7 17.96,16.97 17.96,18.21
VCC12A on TOP: 143.59,43.59 141,43.59 140.59,43.18 140.59,37.59 140.97,37.21 143.31,37.21 143.84,37.74 143.84,43.33
VCC12A on TOP: 111.76,107.57 113.08,107.57 113.36,107.29 113.36,103.73 113.46,103.63 113.69,103.63 113.87,103.45 113.87,103.15 113.56,102.84 111.91,102.84 111.33,103.43 111.33,107.14
VCC12A on TOP: 119.68,10.26 120.09,10.67 120.78,10.67 121.34,11.23 121.34,12.67 121.44,12.78 123.75,12.78 123.95,12.57 126.36,12.57 126.62,12.32 126.62,8.86 126.31,8.56 120.07,8.56 119.68,8.94
VCC12A on TOP: 92.11,17.13 92.28,16.97 92.28,14.27 91.95,13.94 88.16,13.94 87.86,14.25 87.86,16.13 88.86,17.13
VCC12A on TOP: 168.25,26.19 168.25,27.84 168.5,28.09 172.01,28.09 172.72,28.8 174.17,28.8 174.42,28.55 174.42,27.08 173.41,26.06 168.38,26.06
VCC12A on BOTTOM: 159.29,18.8 149.73,18.8 149.1,19.43 149.1,22.48 149.86,23.24 159.21,23.24 159.73,22.73 159.73,19.23
VCC12A on S5: 144.55,44.55 133.81,44.55 126.82,37.57 118.9,37.57 96.66,15.33 96.66,2.94 97.27,2.32 104.08,2.32 109.78,8.03 122.12,8.03 122.67,8.58 130.43,8.58 131.46,9.61 132.75,9.61 142.06,18.92 168.55,18.92 174.29,24.66 174.29,28.83 173.96,29.16 170.89,29.16 165.33,23.6 131.7,23.6 130.48,22.38 130.48,13.31 129.26,12.09 124.1,12.09 123.44,12.75 123.44,32.92 124.92,34.39 144.75,34.39 145.39,35.03 145.39,43.71
VCC12A on V6: 51.23,6.12 50.5,6.86 50.5,10.59 47.14,13.94 20.52,13.94 17.68,16.79 17.68,18.64 17.93,18.9 49.56,18.9 50.14,18.31 61.11,18.31 61.57,17.86 62.66,17.86 63.12,18.31 86.61,18.31 95.96,27.66 128.93,27.66 129.92,28.65 129.92,43.54 130.75,44.36 159.55,44.36 162.51,41.4 185.93,41.4 186.61,42.09 186.61,66.88 176.56,76.94 176.56,80.44 154.99,102.01 129.95,102.01 125.95,106 122.69,106 118.69,102.01 111.28,102.01 110.64,102.64 110.64,106.68 111.35,107.39 118.92,107.39 121.7,110.18 128.88,110.18 131.67,107.39 155.75,107.39 157.2,105.94 163.88,105.94 179.04,90.78 179.04,81.76 193.22,67.59 193.22,27.94 191.36,26.09 165.1,26.09 164.72,25.7 164.72,20.32 160.76,16.36 112.06,16.36 109,19.42 105.26,19.42 104.32,18.47 104.32,17.78 99.06,12.52 89.23,12.52 86.35,9.65 72.59,9.65 69.06,6.12
VCC12A on S8: 40.18,2.34 22.63,2.34 17.96,7.01 17.96,18.21 18.47,18.72 23.93,18.72 28.4,14.25 37.52,14.25 40.88,10.88 40.88,3.04
VCC12A_PM_DDR4_VPP on TOP: 28.02,20.83 28.22,20.62 28.22,19.71 27.84,19.33 21.69,19.33 21.56,19.46 21.56,20.55 21.84,20.83
VCC_EUSB on TOP (solid shape): 164.59,105.66 164.59,104.27 164.21,103.89 163.19,103.89 162.69,103.38 162.69,100.08 161.8,99.19 158.75,99.19 158.19,99.75 158.19,105.31 158.67,105.79 164.47,105.79
VCCIN on TOP: outline of 91 points within 65.91,26.44 100.66,76.14
VCCIN on BOTTOM: 89.84,67.82 95.94,67.82 96.04,67.72 96.04,66.8 96.37,66.47 96.37,65.15 96.52,65 96.85,65 97,64.85 97,63.88 96.85,63.73 96.6,63.73 96.11,63.25 95.48,63.25 95.3,63.42 95.3,63.88 95.12,64.06 93.19,64.06 92.86,63.73 91.39,63.73 91.14,63.98 91.14,65.33 90.93,65.53 90.93,66.29 90.78,66.45 90.2,66.45 89.76,66.88 89.76,67.74
VCCIN on BOTTOM: 92.89,52.37 93.6,52.37 94.16,51.82 95.45,51.82 95.63,51.64 95.63,49.99 94.69,49.05 93.85,49.05 93.57,48.77 92.94,48.77 92.79,48.92 92.79,52.27
VCCIN on BOTTOM: 90.47,73.76 95.05,73.76 95.71,73.1 96.6,73.1 96.77,72.92 96.77,72.11 96.62,71.96 90.35,71.96 90.25,72.06 90.25,72.97 90.37,73.1 90.37,73.66
VCCIN on BOTTOM: 72.69,33.45 72.8,33.55 72.8,33.96 73.15,34.32 73.15,34.85 73.33,35.03 86.59,35.03 88.98,32.64 88.98,31.37 88.62,31.01 85.37,31.01 84.61,30.25 83.69,30.25 83.44,30 83.44,28.85 83.29,28.7 70.66,28.7 70.13,29.24 70.13,30.35 69.49,30.99 66.55,30.99 65.91,31.62 65.91,33.15 66.09,33.32 68.45,33.32 68.58,33.45
VCCIN on G2: 99.82,72.39 99.82,71.01 101.03,69.8 101.03,62.58 98.81,60.36 98.55,60.36 98.23,60.04 98.23,59.79 97.22,58.77 97.22,56.36 96.96,56.11 96.96,51.24 96.9,51.18 95.38,51.18 94.36,50.16 93.85,50.16 93.6,50.42 93.6,57.5 93.41,57.7 93.41,57.82 93.41,58.84 93.41,58.84 93.41,59.41 93.03,59.79 93.03,61.69 93.47,62.14 93.47,63.28 92.96,63.79 92.2,63.79 91.38,64.62 91.38,65.7 91.44,65.76 91.44,66.27 91.38,66.33 91.38,69.11 91.95,69.68 91.95,70.14 91.38,70.71 91.38,73.67 91.57,73.86 95.38,73.86 96.22,73.03 99.19,73.03
VCCIN on S3: 98.11,59.66 98.11,51.63 89.76,43.28 89.76,31.32 88.39,29.95 66.95,29.95 65.46,31.45 65.46,33.68 66.12,34.34 73.28,34.34 90.73,51.79 90.73,59.49 85.92,64.3 85.92,74.61 86.23,74.93 97.38,74.93 99.36,72.95 99.36,69.72 100.03,69.06 100.97,69.06 101.35,68.68 101.35,62.9 ; 1 cut-out
VCCIN on S5: 93.45,63.6 95.71,63.6 96.06,63.25 96.06,50.88 92.66,47.47 92.66,33.02 89.74,30.1 66.19,30.1 65.74,30.56 65.74,33.05 66.67,33.99 74.88,33.99 93.09,52.2 93.09,63.25
VCCIN on V6: 88.67,66.56 88.67,66.85 89.13,67.31 89.13,67.77 88.52,68.38 88.52,72.26 89.03,72.77 94.23,72.77 94.49,72.52 94.49,71.35 106.71,59.13 106.71,36.04 106.05,35.38 91.47,35.38 84.38,28.3 66.14,28.3 65.58,28.85 65.58,33.78 66.24,34.44 77.44,34.44 93.47,50.47 93.47,59.79 92.89,60.38 92.89,61.06 93.34,61.52 93.34,63.75 92.56,64.54 90.69,64.54
VCCIN on V7: 99.26,64.91 99.26,59.47 98.91,59.12 98.91,58.14 99.26,57.78 99.26,54.48 98.8,54.02 98.8,53.08 96.9,51.18 95.38,51.18 94.36,50.16 90.88,50.16 89.84,49.12 89.84,33.58 85.6,29.34 66.47,29.34 65.3,30.51 65.3,44.86 84.79,64.34 84.79,71.86 85.7,72.77 94.23,72.77 94.49,72.52 94.49,71.35 98.34,67.5 98.34,65.83
VCCIN on S8: 101.35,63.73 101.35,62.9 99.07,60.62 99.07,60.6 98.7,60.24 98.7,59.79 98.72,59.78 98.72,44.67 97.38,43.33 97.38,39.73 95.61,37.95 95.61,32.79 92.43,29.62 70.99,29.62 69.65,30.96 66.07,30.96 65.71,31.32 65.71,34.37 66.29,34.95 81.2,34.95 93.85,47.6 93.85,50.16 93.6,50.42 93.6,57.5 93.41,57.7 93.41,59.41 93.03,59.79 93.03,60.36 92.65,60.74 89.47,60.74 85.92,64.3 85.92,71.4 87.86,73.34 87.86,73.79 88.65,74.57 97.75,74.57 98.11,74.22 98.11,66.97
VCCIN on G9: 99.82,72.36 99.82,71.07 101.03,69.86 101.03,62.58 98.81,60.36 98.55,60.36 98.23,60.04 98.23,59.79 97.22,58.77 97.22,56.36 96.29,55.43 96.29,51.44 96.04,51.18 95.38,51.18 94.36,50.16 94,50.16 93.89,50.28 93.89,56.66 94.56,57.34 94.56,58.67 93.43,59.8 93.43,60.23 93.03,60.63 93.03,61.69 93.47,62.14 93.47,63.28 92.96,63.79 92.2,63.79 91.38,64.62 91.38,65.7 91.44,65.76 91.44,66.27 91.38,66.33 91.38,69.13 91.95,69.7 91.95,70.14 91.38,70.71 91.38,73.67 91.57,73.86 95.38,73.86 96.19,73.05 99.14,73.05
VCCIN on S10: 101.35,68.38 101.35,65.41 100.58,64.64 98.55,64.64 96.01,62.1 96.01,58.93 94.51,57.43 94.51,50.32 94.36,50.16 93.85,50.16 93.6,50.42 93.6,57.5 92.89,58.22 92.89,63.2 91.19,64.9 91.19,71.91 90.4,72.69 90.4,73.56 90.7,73.86 95.38,73.86 96.22,73.03 98.7,73.03 99.39,72.34 99.39,70.33
VCCIN on G11: 99.82,71.04 101.03,69.84 101.03,62.58 98.81,60.36 98.55,60.36 98.23,60.04 98.23,59.79 97.22,58.77 97.22,56.36 96.96,56.11 96.96,51.24 96.9,51.18 95.38,51.18 94.36,50.16 93.85,50.16 93.6,50.42 93.6,57.5 93.41,57.7 93.41,57.82 93.41,58.84 93.41,58.84 93.41,59.41 93.03,59.79 93.03,61.69 93.47,62.14 93.47,63.28 92.96,63.79 92.2,63.79 91.38,64.62 91.38,65.7 91.44,65.76 91.44,66.27 91.38,66.33 91.38,69.18 91.92,69.72 91.92,70.04 91.38,70.59 91.38,74.56 91.74,74.93 97.38,74.93 99.82,72.49
VCCIN_P1V05_VCC on TOP: 79.4,10.87 81.64,10.87 83.13,9.37 83.13,7.85 82.8,7.52 82.37,7.52 81.99,7.9 81.13,7.9 80.85,7.62 79.48,7.62 79.22,7.87 79.22,10.69
VCCKRHV on TOP: 140.79,69.42 142.32,69.42 142.44,69.29 142.44,65.48 142.06,65.1 139.75,65.1 139.14,65.71 139.14,67.61 139.47,67.94 140.34,67.94 140.67,68.28 140.67,69.29
VCCKRHV on BOTTOM: 121.11,69.16 120.83,68.88 120.83,65.3 121.26,64.87 141.25,64.87 141.73,65.35 141.73,68.55 141.12,69.16
VCCKRHV on S8: 122.28,70.1 108.2,70.1 107.16,69.06 107.16,65.71 107.49,65.38 122.35,65.38 123.01,66.04 123.01,69.34 122.28,70.08
VCCSCFUSESUS on TOP: 130.43,70.74 130.43,69.85 129.67,69.09 129.67,68.07 129.54,67.94 128.52,67.94 128.27,68.2 128.27,70.48 128.65,70.87 130.3,70.87
VCCSCFUSESUS on TOP: 144.73,69.55 145.62,69.55 146.38,68.78 147.4,68.78 147.52,68.66 147.52,66.57 146.96,66.01 145.19,66.01 144.96,66.24 144.96,67.41 144.6,67.77 144.6,69.42
VCCSCFUSESUS on TOP: 152.2,61.34 151.38,62.15 151.38,63.8 151.79,64.21 168.4,64.21 168.78,63.83 168.78,61.87 168.25,61.34
VCCSCFUSESUS on S5: 107.42,69.06 101.96,69.06 101.73,68.83 101.73,64.19 102.29,63.63 114.07,63.63 115.83,61.87 118.87,61.87 120.63,63.63 145.39,63.63 148.18,60.83 155.68,60.83 156.26,61.42 156.26,67.49 155.85,67.89 132,67.89 129.82,70.08 124.1,70.08 123.01,68.99 107.49,68.99
VCCSUS3_3 on S8: 93.47,75.87 92.13,77.22 92.13,84 92.48,84.35 96.27,84.35 96.27,84.4 96.93,85.06 96.93,86.92 97.16,87.15 97.97,87.15 98.04,87.07 98.04,83.57 97.26,82.78 96.29,82.78 96.28,82.79 94.41,80.92 94.41,79.65 95.05,79.02 97.71,79.02 97.82,78.92 97.82,76.3 97.38,75.87
VCCSUS3_3 on S10: 98.3,86.11 98.22,86.19 95.28,86.19 93.47,84.38 93.47,76.33 93.95,75.84 97.38,75.84 97.82,76.28 97.82,78.89 97.71,78.99 96.52,78.99 96.22,79.3 96.22,80.7 96.69,81.17 96.69,82.84 98.3,84.45
DDR4_VPP on TOP: 44.3,37.11 46.23,37.11 46.43,36.91 46.43,35.64 46.28,35.48 44.5,35.48 44.2,35.79 44.2,37.01
DDR4_VPP on TOP: 32.3,37.11 34.23,37.11 34.43,36.91 34.43,35.64 34.28,35.48 32.5,35.48 32.2,35.79 32.2,37.01
DDR4_VPP on TOP: 20.95,31.34 32.66,31.34 34.29,29.72 34.29,28.52 33.99,28.22 20.95,28.22 20.7,28.47 20.7,31.09
DDR4_VPP on BOTTOM: 25.78,31.24 32.38,31.24 34.04,29.59 34.04,28.57 33.4,27.94 25.53,27.94 25.27,28.19 25.27,30.73
DDR4_VPP on S10: 32.23,36.47 46,36.47 46.23,36.25 46.23,35.46 42.55,31.78 40.74,31.78 38.61,29.64 38.61,18.52 38.2,18.11 29.36,18.11 27.15,20.32 27.15,32.89 24.99,35.05 24.99,50.55 25.37,50.93 29.21,50.93 29.95,50.19 29.95,38.76
DDR4_VPP_AGND on S8: 31.98,22.45 35.69,22.45 38.4,19.74 38.4,19.1 37.31,18.01 30.02,18.01 29.41,18.62 29.41,19.89
DDR4_VPP_SW on TOP: 21.51,25.93 24.38,25.93 25.12,25.2 25.12,24.28 26.67,22.73 28.19,22.73 28.32,22.61 28.32,21.67 28.17,21.51 25.45,21.51 24.94,22.02 20.7,22.02 20.45,22.28 20.45,24.87
HS1_PIN1 on TOP (solid shape): outline of 268 points within 120.03,97.06 128.92,105.94
HS1_PIN1 on BOTTOM (solid shape): outline of 268 points within 120.03,97.06 128.92,105.94
HS1_PIN2 on TOP (solid shape): outline of 268 points within 120.03,37.06 128.92,45.94
HS1_PIN2 on BOTTOM (solid shape): outline of 268 points within 120.03,37.06 128.92,45.94
HS1_PIN3 on TOP (solid shape): outline of 268 points within 60.03,97.06 68.92,105.94
HS1_PIN3 on BOTTOM (solid shape): outline of 268 points within 60.03,97.06 68.92,105.94
HS1_PIN4 on TOP (solid shape): outline of 268 points within 60.03,37.06 68.92,45.94
HS1_PIN4 on BOTTOM (solid shape): outline of 268 points within 60.03,37.06 68.92,45.94
NUT1_GND on TOP (solid shape): outline of 258 points within 186.65,90.75 195.15,99.25
PS_12V_LVIN1 on TOP (solid shape): 70.98,18.49 67.58,18.49 67.58,20.12 70.98,20.12
PS_12V_LVIN1 on BOTTOM (solid shape): 85.52,20.09 85.52,18.67 85.34,18.49 80.62,18.49 80.59,18.52 80.59,20.19 80.72,20.32 85.29,20.32
PS_12V_LVIN1 on TOP: 67.21,20.19 70.97,20.19 71.04,20.12 71.04,18.52 70.94,18.41 70.36,18.41 70.05,18.11 70.05,13.84 69.75,13.54 68.28,13.54 68.02,13.79 68.02,16.64 67.56,17.09 64.82,17.09 64.44,17.48 64.44,19.48 64.69,19.74 66.75,19.74
PS_12V_LVIN1 on TOP: 82.02,20.52 85.27,20.52 85.5,20.29 85.5,18.75 85.19,18.44 84.63,18.44 84.48,18.29 84.48,16.74 84.79,16.43 86.28,16.43 86.51,16.21 86.51,14.17 86.89,13.79 87.76,13.79 88.21,13.34 88.21,11.53 87.83,11.14 86.54,11.14 86.41,11.27 86.41,13.18 85.93,13.67 82.73,13.67 82.37,14.02 82.37,17.7 81.81,18.26 81.81,20.32
PS_12V_LVIN1 on BOTTOM: 70.84,20.14 68.68,20.14 68.12,19.58 65.99,19.58 65.79,19.79 64.44,19.79 64.24,19.58 64.24,17.81 64.54,17.5 70.76,17.5 71.04,17.78 71.04,19.94
PS_12V_LVIN1 on S10: 85.37,20.45 68.81,20.45 68.25,19.89 68.25,19.2 70.03,17.42 84.07,17.42 85.7,19.05 85.7,20.12
PS_12V_LVIN3 on TOP: 119.94,12.73 119.94,11.25 118.01,9.32 115.8,9.32 115.57,9.55 115.57,14.53 114,16.1 110.36,16.1 110.11,16.36 110.11,18.21 110.41,18.52 118.24,18.52 118.31,18.44 118.31,16.87 117.98,16.54 117.5,16.54 117.3,16.33 117.3,13.49 117.75,13.03 119.63,13.03
RP_1.05V_REG_PHASE on TOP: 120.55,20.9 120.37,21.08 115.7,21.08 115.44,21.34 115.44,26.42 115.95,26.92 122.05,26.92 122.43,26.54 122.43,22.12 121.21,20.9
RP_1.8V_REG_PHASE1 on TOP: 91.03,30.45 94.49,30.45 94.77,30.18 94.77,22.2 94.26,21.69 89.56,21.69 88.32,22.94 83.01,22.94 82.73,23.22 82.73,23.98 84.79,26.04 89.76,26.04 90.27,26.54 90.27,29.69
RP_1.8V_REG_PHASE1 on BOTTOM, S5: 86,27.84 88.85,27.84 89.31,27.38 89.31,25.32 87.38,23.39 84.3,23.39 84.02,23.67 84.02,24.74 85.6,26.31 85.6,27.43
RP_1.8V_REG_PHASE2 on TOP: 66.34,30.2 69.34,30.2 69.7,29.84 69.7,25.91 70.54,25.07 75.79,25.07 77.77,23.09 77.77,21.89 77.62,21.74 76.33,21.74 75.31,22.76 67.41,22.76 65.96,24.21 65.96,29.82
RP_1.8V_REG_PHASE2 on BOTTOM: 66.17,27.58 68.99,27.58 69.24,27.33 69.24,25.91 70.61,24.54 71.86,24.54 72.29,24.1 72.29,23.04 72.09,22.83 67.44,22.83 65.99,24.28 65.99,27.41
RP_1.8V_REG_V18A on S10: 86.94,16.66 88.32,18.03 89.31,18.03 89.61,17.73 89.61,14.66 88.52,13.56 82.22,13.56 77.85,9.19 77.85,6.53 76.78,5.46 71.07,5.46 70.66,5.87 70.66,7.54 71.2,8.08 71.2,14.88 72.97,16.66
RP_3.3V_LVCC on TOP: 205.61,80.34 205.61,78.14 205.96,77.79 205.96,74.52 206.1,74.38 207.62,74.38 207.81,74.57 207.81,80.45 207.68,80.58 205.85,80.58
RP_3.3V_LVCC on BOTTOM: 208.03,108.99 208.28,108.74 208.28,106.83 207.9,106.45 206.6,106.45 206.35,106.71 206.35,108.74 206.6,108.99
RP_3.3V_LVCC on BOTTOM: 188.81,109.03 189.99,109.03 190.24,108.78 190.24,106.75 190.14,106.65 188.59,106.65 188.26,106.98 188.26,108.49
RP_3.3V_LVCC on V7: 189.38,109.61 207.18,109.61 207.98,108.82 207.98,79.47 207.29,78.79 205.69,78.79 204.93,79.56 204.93,105.1 203.95,106.08 188.85,106.08 188,106.93 188,108.23
RP_BAT_3.3V on BOTTOM: 7.61,104.2 6.89,104.92 6.89,110.94 7.67,111.72 14.64,111.72 15.49,110.87 15.49,105.18 14.52,104.2
SW_VDDQ_CH01 on TOP (solid shape): 57.75,23.57 55.5,23.57 55.5,24.55 57.75,24.55
SW_VDDQ_CH01 on TOP: 59.08,23.6 58.95,23.47 55.55,23.47 55.07,23.95 55.07,26.04 57.68,28.65 60.73,28.65 61.24,28.14 61.24,25.98 60.67,25.41 60.21,25.41 59.08,24.28

Small or netless copper shapes (teardrops, artwork), in the pictures only: 115 on TOP

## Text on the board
Ref Des/Silkscreen Bottom: 02 | 03
Ref Des/Silkscreen Top: 01 | SYS | P5V | P3V3 | P1V7 | P1V3 | P1V05 | DDR4_VPP | VDDQ | VTT | P1V5 | VCCIN | P/N:142000001998A REV.01
PAGE_OUTLINE: 02/18/2019
User.9: TOP (COMPONENT_SIDE)                       1
User.10: G2 (GND_LAYER_2)                           2
User.11: G5 (GND_LAYER_5)                           5
User.12: BOT (SOLDER_SIDE)                         12
User.13: SST (SILKSCREEN_TOP)                      13
User.14: SSB (SILKSCREEN_BOTTOM)                   14
User.15: SMT (SOLDER_MASK_TOP)                     15
User.16: SMB (SOLDER_MASK_BOTTOM)                  16
User.17: Finish Hole Size=177mil,Number of Visible hole=4 | DRILL(FINISH HOLE SIZE LIST)                  20
User.18: PMT (PASTE_MASK_TOP)                     17
User.19: PMB (PASTE_MASK_BOTTOM)                  18
User.20: DIM (BOARD_DIMENSION)                    19
User.21: S3 (SIGNAL_LAYER_3)                       3
User.22: S4 (SIGNAL_LAYER_4 )                      4
User.23: V6 (VCC_LAYER_6)                           6
User.24: V7 (VCC_LAYER_7)                           7
User.25: G8 (GND_LAYER_8)                           8
User.26: S9 (SIGNAL_LAYER_9)                       9
User.27: S10 (SIGNAL)LAYER_10)                     10
User.28: G11 (GND_LAYER_11)                         11
User.29: S8 (SIGNAL_LAYER_8)                       8
User.30: S5 (SIGNAL_LAYER_5)                       5
User.31: G4 (GND_LAYER_4)                           4
User.32: G9 (GND_LAYER_9)                           9
